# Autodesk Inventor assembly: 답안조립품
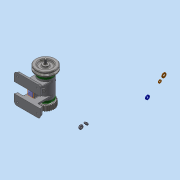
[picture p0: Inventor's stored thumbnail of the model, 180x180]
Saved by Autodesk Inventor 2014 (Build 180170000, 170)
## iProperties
Created: 2016-07
Part Number: 답안조립품
Document SubType Name: Assembly
Designer: 406-9
Author: 406-9
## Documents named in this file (16)
- C:\Users\406-9\Desktop\460707V1009\답안조립품.iam
- C:\Users\406-9\Desktop\460707V1009\본체.ipt
- C:\Users\406-9\Desktop\460707V1009\460707V1009\V벨트풀리.ipt
- C:\Users\406-9\Desktop\460707V1009\460707V1009\너트 M 8.ipt
- C:\Users\406-9\Desktop\460707V1009\460707V1009\니플 M 6 x 0.75.ipt
- C:\Users\406-9\Desktop\460707V1009\460707V1009\베어링 15 x 32 x 9.ipt
- C:\Users\406-9\Desktop\460707V1009\460707V1009\볼트 M 6 x 8.ipt
- C:\Users\406-9\Desktop\460707V1009\460707V1009\볼트 M4 x 12.ipt
- C:\Users\406-9\Desktop\460707V1009\460707V1009\스퍼기어.ipt
- C:\Users\406-9\Desktop\460707V1009\460707V1009\스프링와셔 8.ipt
- C:\Users\406-9\Desktop\460707V1009\460707V1009\오일 실 15 25 7.ipt
- C:\Users\406-9\Desktop\460707V1009\460707V1009\와셔 6x11.5.ipt
- C:\Users\406-9\Desktop\460707V1009\460707V1009\와셔 8x17.ipt
- C:\Users\406-9\Desktop\460707V1009\460707V1009\축.ipt
- C:\Users\406-9\Desktop\460707V1009\460707V1009\커버.ipt
- C:\Users\406-9\Desktop\460707V1009\460707V1009\키 3 x 3 x 12.ipt
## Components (11 placed, 3 different names)
1. KS B 2023 6002 - 15 x 32 x 9:1
2. KS B 2023 6002 - 15 x 32 x 9:2
3. V벨트풀리:2
4. ISO 4762 M4 x 12:2
5. ISO 4762 M4 x 12:3
6. ISO 4762 M4 x 12:4
7. ISO 4762 M4 x 12:5
8. ISO 4762 M4 x 12:1
9. ISO 4762 M4 x 12:6
10. ISO 4762 M4 x 12:7
11. ISO 4762 M4 x 12:8
## Named parameters: d7_d6 = 0
